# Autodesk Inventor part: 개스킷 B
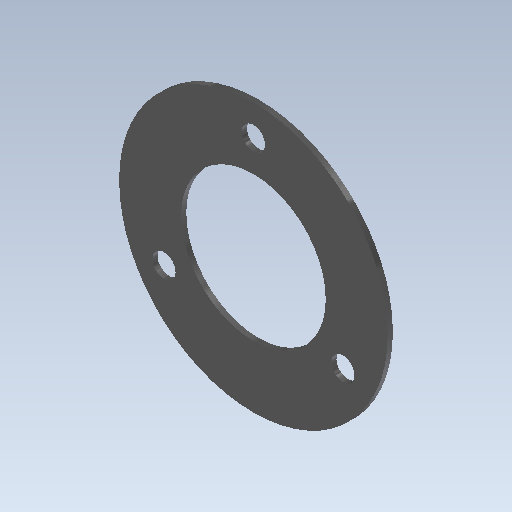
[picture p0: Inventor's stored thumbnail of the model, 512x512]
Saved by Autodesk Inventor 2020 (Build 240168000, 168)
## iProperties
Created: 2020-04
Part Number: 개스킷 B
Material: 고무
Document SubType Name: Modeling
Designer: mduedu
Density: 0.93 g/cm^3
Mass: 1.35803 g
Surface Area: 32.1424 cm^2
Volume: 1.46025 cm^3
Appearance: 고무 - 검은색 - 버전 1.1
Author: mduedu
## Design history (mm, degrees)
sketch "스케치1"
  geometry: C1 r 26 at (0, 0); 1 further point
  constraints: 1 centre point, 1 coincident
  dimensions: "d0" = 52 diameter of C1
extrude "돌출1" new body sketch "스케치1" distance "d1" = 1; taper "d2" = 0 deg
sketch "스케치3" dims "d6" = 40
  geometry: 3 further points
  constraints: 2 vertical alignment, 1 coincident, 2 other
hole "구멍1" sketch "스케치3" at (0, 20) diameter "d7" = 4.5; stored, may be unused: countersink angle "d11" = 90 deg, drill point angle "d13" = 118 deg; dims "d8" = 6, "d9" = 4, "d10" = 2, "d12" = 8
sketch "스케치4"
  geometry: C1 r 14 at (0, 0); 1 further point
  constraints: 1 centre point, 1 coincident
  dimensions: "d17" = 28 diameter of C1
extrude "돌출3" cut sketch "스케치4" extent not by distance; stored distance "d18" = 1; taper "d19" = 0 deg
node "솔리드1"
pattern_circular "원형 패턴1" dims angle "d15" = 360 deg
